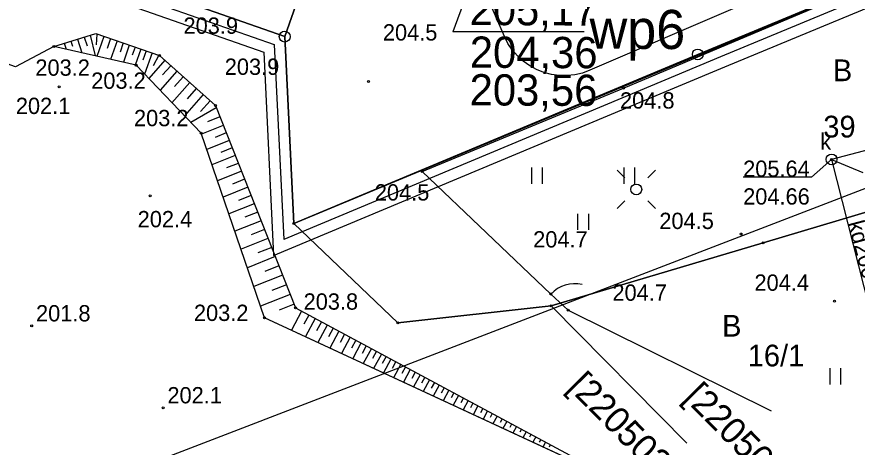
# Model space of a CAD drawing. Extents: x 6512606 to 6513347, y 6022524 to 6022728.
# Drawn here: x 6512793.86 to 6512832.56, y 6022553.23 to 6022573.02 of the extents above; entities that cross this region are included whole.
import ezdxf

# ---------------------------------------------------------------- set-up
doc = ezdxf.new("R2010")
doc.units = 0
for name, color, linetype in [('000 Inne (niezydentyfikowane)', 7, 'Continuous'), ('20', 7, 'Continuous'), ('202-punkt graniczny', 7, 'Continuous'), ('203-punkt graniczny', 7, 'Continuous'), ('208-opis obrębu', 7, 'Continuous'), ('210-oznaczenie konturu użytku gruntowego', 7, 'Continuous'), ('211-numer działki ewidencyjnej', 7, 'Continuous'), ('216-obręb ewidencyjny', 7, 'Continuous'), ('217-kontur klasyfikacyjny', 7, 'Continuous'), ('218-kontur użytku gruntowego', 7, 'Continuous'), ('219-działka ewidencyjna', 7, 'Continuous'), ('4', 7, 'Continuous'), ('940-Trawnik symb.', 7, 'Continuous'), ('940-Trawnik symb. poj.', 7, 'Continuous'), ('Default', 7, 'Continuous'), ('furtka', 7, 'Continuous'), ('kolor_kostka_bet', 7, 'Continuous'), ('latarnia na słupie lub maszcie (punkt)', 7, 'Continuous'), ('Level 47', 7, 'Continuous'), ('maxp_ramka_2', 7, 'Continuous'), ('Obszar opracowania', 7, 'Continuous'), ('ogrodzenie trwałe', 7, 'Continuous'), ('pikieta naturalna', 7, 'Continuous'), ('pikieta naturalna-Atr2', 7, 'Continuous'), ('przewód kanalizacyjny (linia)', 7, 'Continuous'), ('przewód kanalizacyjny (linia)-Atr1', 7, 'Continuous'), ('punkt o określonej wysokości (sieć kanalizacyjna)', 7, 'Continuous'), ('punkt o określonej wysokości (sieć kanalizacyjna)-Atr2', 7, 'Continuous'), ('punkt o określonej wysokości (sieć kanalizacyjna)-Atr3', 7, 'Continuous'), ('punkt wysokościowy naturalny', 7, 'Continuous'), ('punkt wysokościowy naturalny-Atr2', 7, 'Continuous'), ('skarpa nieumocniona', 7, 'Continuous'), ('słup (punkt)', 7, 'Continuous'), ('urządzenie techniczne projektowane lub w budowie (sieć kanalizacyjna) - powierzchnia - ob. projektowany', 7, 'Continuous'), ('woda stojąca', 7, 'Continuous'), ('właz okrągły - siec kanalizacyjna (punkt)', 7, 'Continuous'), ('właz okrągły - siec kanalizacyjna (punkt)-Atr17', 7, 'Continuous')]:
    doc.layers.add(name, color=color, linetype=linetype)

# ---------------------------------------------------------------- blocks, each defined once
blk = doc.blocks.new('202')
at = {"layer": 'Default'}
blk.add_circle((0, 0), 2.5, dxfattribs=at)
blk = doc.blocks.new('203')
at = {"layer": 'Default'}
blk.add_circle((0, 0), 0.45, dxfattribs=at)
blk = doc.blocks.new('PW01')
at = {"layer": 'Default'}
blk.add_circle((0, 0), 0.45, dxfattribs=at)
blk = doc.blocks.new('940')
at = {"layer": 'Default'}
for p, q in [((-23.74, 17.49), (-23.74, 24.99)), ((-18.74, 17.49), (-18.74, 24.99)), ((18.74, 17.49), (18.74, 24.99)), ((23.74, 17.49), (23.74, 24.99)), ((-2.5, -3.75), (-2.5, 3.75)), ((2.5, -3.75), (2.5, 3.75))]:
    blk.add_line(p, q, dxfattribs=at)
blk = doc.blocks.new('SM04')
at = {"layer": 'Default'}
blk.add_circle((0, 0), 2.5, dxfattribs=at)
blk = doc.blocks.new('SM011')
at = {"layer": 'Default'}
for p, q in [((-5.3, 5.31), (-8.83, 8.84)), ((5.31, 5.31), (8.84, 8.84)), ((-5.3, -5.3), (-8.83, -8.83)), ((5.31, -5.3), (8.84, -8.83))]:
    blk.add_line(p, q, dxfattribs=at)
blk = doc.blocks.new('US22')
at = {"layer": 'Default'}
blk.add_circle((0, 0), 2.5, dxfattribs=at)
blk = doc.blocks.new('940P')
at = {"layer": 'Default'}
for p, q in [((-2.5, -3.75), (-2.5, 3.75)), ((2.5, -3.75), (2.5, 3.75))]:
    blk.add_line(p, q, dxfattribs=at)
blk = doc.blocks.new('OK04')
at = {"layer": 'Default'}
blk.add_arc((15, 0.01), 15, 120, 180, dxfattribs=at)

msp = doc.modelspace()

# ---------------------------------------------------------------- linework, layer by layer
at = {"layer": '000 Inne (niezydentyfikowane)'}
for p, q in [((6512796.97, 6022572.09), (6512797.1, 6022571.69)), ((6512797.25, 6022572.17), (6512797.48, 6022571.22)), ((6512797.55, 6022572.23), (6512797.52, 6022571.73)), ((6512797.87, 6022572.12), (6512797.55, 6022571.2)), ((6512796.05, 6022571.81), (6512796.13, 6022571.53)), ((6512796.36, 6022571.9), (6512796.43, 6022571.67)), ((6512796.66, 6022571.99), (6512796.86, 6022571.36)), ((6512798.18, 6022572.02), (6512798.02, 6022571.57)), ((6512798.48, 6022571.91), (6512798.18, 6022571.06)), ((6512798.76, 6022571.82), (6512798.62, 6022571.4)), ((6512799.04, 6022571.72), (6512798.77, 6022570.93)), ((6512799.31, 6022571.63), (6512799.18, 6022571.25)), ((6512799.57, 6022571.54), (6512799.31, 6022570.8)), ((6512799.82, 6022571.45), (6512799.67, 6022571.03)), ((6512800.09, 6022571.36), (6512799.75, 6022570.38)), ((6512800.68, 6022571.02), (6512799.94, 6022570.19)), ((6512800.4, 6022571.25), (6512800.14, 6022570.76)), ((6512801.24, 6022570.52), (6512800.46, 6022569.64)), ((6512800.96, 6022570.77), (6512800.58, 6022570.35)), ((6512801.53, 6022570.26), (6512801.13, 6022569.81)), ((6512801.83, 6022570), (6512801, 6022569.07)), ((6512802.13, 6022569.72), (6512801.71, 6022569.25)), ((6512802.45, 6022569.44), (6512801.58, 6022568.47)), ((6512802.77, 6022569.16), (6512802.32, 6022568.66)), ((6512803.05, 6022568.83), (6512801.88, 6022568.16)), ((6512803.22, 6022568.42), (6512802.64, 6022568.19)), ((6512803.37, 6022568.02), (6512802.37, 6022567.63)), ((6512803.51, 6022567.68), (6512803, 6022567.47)), ((6512803.65, 6022567.33), (6512802.61, 6022566.92)), ((6512803.92, 6022566.64), (6512802.85, 6022566.21)), ((6512803.78, 6022566.99), (6512803.26, 6022566.78)), ((6512804.06, 6022566.28), (6512803.52, 6022566.07)), ((6512804.21, 6022565.92), (6512803.1, 6022565.48)), ((6512804.35, 6022565.55), (6512803.79, 6022565.33)), ((6512804.5, 6022565.18), (6512803.36, 6022564.73)), ((6512804.65, 6022564.8), (6512804.07, 6022564.57)), ((6512804.8, 6022564.42), (6512803.63, 6022563.96)), ((6512804.96, 6022564.03), (6512804.36, 6022563.8)), ((6512805.11, 6022563.64), (6512803.9, 6022563.16)), ((6512805.27, 6022563.23), (6512804.66, 6022562.99)), ((6512805.43, 6022562.83), (6512804.19, 6022562.33)), ((6512805.6, 6022562.41), (6512804.96, 6022562.16)), ((6512805.76, 6022561.99), (6512804.48, 6022561.48)), ((6512805.93, 6022561.57), (6512805.28, 6022561.31)), ((6512806.1, 6022561.13), (6512804.78, 6022560.61)), ((6512806.28, 6022560.69), (6512805.61, 6022560.43)), ((6512806.45, 6022560.25), (6512805.09, 6022559.71)), ((6512806.63, 6022559.8), (6512805.94, 6022559.52)), ((6512806.98, 6022559.48), (6512806.51, 6022558.6)), ((6512807.31, 6022559.3), (6512807.08, 6022558.88)), ((6512807.6, 6022559.15), (6512807.15, 6022558.31)), ((6512807.89, 6022558.99), (6512807.67, 6022558.58)), ((6512808.16, 6022558.84), (6512807.73, 6022558.04)), ((6512808.43, 6022558.7), (6512808.22, 6022558.3)), ((6512808.7, 6022558.56), (6512808.28, 6022557.78)), ((6512808.96, 6022558.42), (6512808.76, 6022558.04)), ((6512809.22, 6022558.28), (6512808.82, 6022557.53)), ((6512809.47, 6022558.15), (6512809.27, 6022557.78)), ((6512809.71, 6022558.01), (6512809.33, 6022557.3)), ((6512809.95, 6022557.89), (6512809.76, 6022557.53)), ((6512810.19, 6022557.76), (6512809.82, 6022557.07)), ((6512810.42, 6022557.64), (6512810.24, 6022557.3)), ((6512810.65, 6022557.51), (6512810.29, 6022556.85)), ((6512810.87, 6022557.39), (6512810.69, 6022557.07)), ((6512811.09, 6022557.27), (6512810.75, 6022556.64)), ((6512811.31, 6022557.16), (6512811.15, 6022556.84)), ((6512811.54, 6022557.04), (6512811.21, 6022556.42)), ((6512811.76, 6022556.92), (6512811.6, 6022556.62)), ((6512811.98, 6022556.8), (6512811.67, 6022556.21)), ((6512812.2, 6022556.68), (6512812.05, 6022556.39)), ((6512812.43, 6022556.56), (6512812.13, 6022556)), ((6512812.65, 6022556.44), (6512812.5, 6022556.17)), ((6512812.87, 6022556.32), (6512812.58, 6022555.79)), ((6512813.09, 6022556.2), (6512812.95, 6022555.94)), ((6512813.31, 6022556.08), (6512813.04, 6022555.57)), ((6512813.54, 6022555.96), (6512813.4, 6022555.71)), ((6512813.76, 6022555.84), (6512813.5, 6022555.36)), ((6512813.98, 6022555.72), (6512813.86, 6022555.49)), ((6512814.2, 6022555.6), (6512813.96, 6022555.15)), ((6512814.43, 6022555.49), (6512814.31, 6022555.26)), ((6512814.65, 6022555.37), (6512814.42, 6022554.94)), ((6512814.87, 6022555.25), (6512814.76, 6022555.04)), ((6512815.09, 6022555.13), (6512814.88, 6022554.72)), ((6512815.32, 6022555.01), (6512815.21, 6022554.81)), ((6512815.54, 6022554.89), (6512815.34, 6022554.51)), ((6512815.76, 6022554.77), (6512815.66, 6022554.59)), ((6512815.98, 6022554.65), (6512815.79, 6022554.3)), ((6512816.21, 6022554.53), (6512816.12, 6022554.36)), ((6512816.43, 6022554.41), (6512816.25, 6022554.08)), ((6512816.65, 6022554.29), (6512816.57, 6022554.13)), ((6512816.87, 6022554.17), (6512816.71, 6022553.87)), ((6512817.1, 6022554.05), (6512817.02, 6022553.91)), ((6512817.32, 6022553.93), (6512817.17, 6022553.66)), ((6512817.54, 6022553.81), (6512817.47, 6022553.68)), ((6512817.76, 6022553.7), (6512817.63, 6022553.45)), ((6512817.99, 6022553.58), (6512817.92, 6022553.46)), ((6512818.21, 6022553.46), (6512818.09, 6022553.23)), ((6512818.43, 6022553.34), (6512818.37, 6022553.23))]:
    msp.add_line(p, q, dxfattribs=at)
at = {"layer": '20'}
for p in [(6512818.017, 6022583.64), (6512819.992, 6022572.326)]:
    msp.add_line(p, (6512813.949, 6022572.326), dxfattribs=at)
at = {"layer": '216-obręb ewidencyjny'}
for points in [[(6512836.687, 6022675.173), (6512833.61, 6022675.02), (6512828.67, 6022670.98), (6512801.96, 6022670.34), (6512810.18, 6022663.28), (6512825.37, 6022649.66), (6512838.47, 6022634.29), (6512852.25, 6022608.25), (6512853.17, 6022604.51), (6512855.78, 6022583.95), (6512858.85, 6022571.74), (6512828.23, 6022562.62), (6512818.47, 6022559.72), (6512824.714, 6022553.406)], [(6512728.286, 6022540.131), (6512737.69, 6022552.74), (6512751.08, 6022569.37), (6512775.81, 6022564.08), (6512780.7, 6022581.02), (6512806.2, 6022572.11), (6512806.62, 6022563.51), (6512811.41, 6022558.95), (6512818.47, 6022559.72), (6512828.23, 6022562.62), (6512858.85, 6022571.74), (6512855.78, 6022583.95), (6512853.17, 6022604.51), (6512852.25, 6022608.25), (6512838.47, 6022634.29)], [(6512824.714, 6022553.406), (6512818.47, 6022559.72), (6512811.41, 6022558.95), (6512806.62, 6022563.51), (6512806.2, 6022572.11), (6512780.7, 6022581.02), (6512775.81, 6022564.08), (6512751.08, 6022569.37)]]:
    msp.add_lwpolyline(points, dxfattribs=at)
at = {"layer": '217-kontur klasyfikacyjny'}
for points in [[(6512811.09, 6022586.02), (6512806.2, 6022572.11)], [(6512825.22, 6022571.29), (6512855.78, 6022583.95)], [(6512806.2, 6022572.11), (6512806.62, 6022563.51)], [(6512806.62, 6022563.51), (6512825.22, 6022571.29)]]:
    msp.add_lwpolyline(points, dxfattribs=at)
at = {"layer": '218-kontur użytku gruntowego'}
for points in [[(6512806.2, 6022572.11), (6512811.09, 6022586.02)], [(6512811.09, 6022586.02), (6512806.2, 6022572.11)], [(6512825.22, 6022571.29), (6512855.78, 6022583.95)], [(6512855.78, 6022583.95), (6512825.22, 6022571.29)], [(6512780.7, 6022581.02), (6512806.2, 6022572.11)], [(6512806.2, 6022572.11), (6512780.7, 6022581.02)], [(6512806.2, 6022572.11), (6512806.62, 6022563.51)], [(6512806.62, 6022563.51), (6512806.2, 6022572.11)], [(6512858.85, 6022571.74), (6512828.23, 6022562.62)], [(6512828.23, 6022562.62), (6512858.85, 6022571.74)], [(6512806.62, 6022563.51), (6512825.22, 6022571.29)], [(6512825.22, 6022571.29), (6512806.62, 6022563.51)], [(6512806.62, 6022563.51), (6512811.41, 6022558.95)], [(6512811.41, 6022558.95), (6512806.62, 6022563.51)], [(6512828.23, 6022562.62), (6512818.47, 6022559.72)], [(6512818.47, 6022559.72), (6512828.23, 6022562.62)], [(6512811.41, 6022558.95), (6512818.47, 6022559.72)], [(6512818.47, 6022559.72), (6512811.41, 6022558.95)], [(6512818.47, 6022559.72), (6512824.714, 6022553.406)], [(6512824.714, 6022553.406), (6512818.47, 6022559.72)]]:
    msp.add_lwpolyline(points, dxfattribs=at)
at = {"layer": '219-działka ewidencyjna'}
for points in [[(6512811.09, 6022586.02), (6512806.2, 6022572.11)], [(6512825.22, 6022571.29), (6512855.78, 6022583.95)], [(6512780.7, 6022581.02), (6512806.2, 6022572.11)], [(6512806.2, 6022572.11), (6512806.62, 6022563.51)], [(6512858.85, 6022571.74), (6512828.23, 6022562.62)], [(6512825.22, 6022571.29), (6512806.62, 6022563.51)], [(6512806.62, 6022563.51), (6512811.41, 6022558.95)], [(6512828.23, 6022562.62), (6512818.47, 6022559.72)], [(6512818.47, 6022559.72), (6512811.41, 6022558.95)], [(6512818.47, 6022559.72), (6512824.714, 6022553.406)]]:
    msp.add_lwpolyline(points, dxfattribs=at)
at = {"layer": '4'}
for points in [[(6512811.09, 6022586.02), (6512806.2, 6022572.11)], [(6512825.22, 6022571.29), (6512855.78, 6022583.95)], [(6512780.7, 6022581.02), (6512806.2, 6022572.11)], [(6512806.2, 6022572.11), (6512806.62, 6022563.51)], [(6512858.85, 6022571.74), (6512828.23, 6022562.62)], [(6512825.22, 6022571.29), (6512806.62, 6022563.51)], [(6512806.62, 6022563.51), (6512811.41, 6022558.95)], [(6512828.23, 6022562.62), (6512818.47, 6022559.72)], [(6512818.47, 6022559.72), (6512811.41, 6022558.95)], [(6512818.47, 6022559.72), (6512824.714, 6022553.406)]]:
    msp.add_lwpolyline(points, dxfattribs=at)
at = {"layer": 'furtka'}
msp.add_lwpolyline([(6512818.46, 6022560.27), (6512819.25, 6022559.53)], dxfattribs=at)
at = {"layer": 'kolor_kostka_bet'}
msp.add_lwpolyline([(6512773.05, 6022582.65), (6512780.7, 6022581.02), (6512806.2, 6022572.11), (6512806.62, 6022563.51), (6512855.78, 6022583.95)], dxfattribs=at)
msp.add_lwpolyline([(6512773.05, 6022582.65), (6512780.7, 6022581.02), (6512806.2, 6022572.11), (6512806.62, 6022563.51), (6512855.78, 6022583.95)], dxfattribs=at)
at = {"layer": 'maxp_ramka_2'}
for points in [[(6512856.423, 6022583.675), (6512826.273, 6022571.185), (6512822.563, 6022569.637), (6512806.155, 6022562.774)], [(6512805.691, 6022562.037), (6512822.756, 6022569.175), (6512826.465, 6022570.723), (6512855.56, 6022582.776)], [(6512780.565, 6022580.538), (6512805.717, 6022571.749), (6512806.155, 6022562.774)], [(6512780.43, 6022580.055), (6512805.234, 6022571.388), (6512805.691, 6022562.037)]]:
    msp.add_lwpolyline(points, dxfattribs=at)
at = {"layer": 'Obszar opracowania'}
msp.add_lwpolyline([(6512710.98, 6022693.84), (6512748.35, 6022694.16), (6512798.11, 6022695.25), (6512807.47, 6022695.46), (6512809.66, 6022606.87), (6512863.71, 6022622.03), (6512875.13, 6022581.36), (6512755.22, 6022535.25), (6512691.61, 6022568.03), (6512709.16, 6022605.16)], close=True, dxfattribs=at)
at = {"layer": 'ogrodzenie trwałe'}
for points in [[(6512818.46, 6022560.27), (6512812.53, 6022565.9), (6512821.8, 6022569.74), (6512835.02, 6022575.32), (6512844.28, 6022579.16), (6512845.12, 6022578.38)], [(6512819.25, 6022559.53), (6512828.604, 6022554.902)]]:
    msp.add_lwpolyline(points, dxfattribs=at)
at = {"layer": 'przewód kanalizacyjny (linia)'}
for points in [[(6512843.16, 6022569.56), (6512831.38, 6022566.46)], [(6512831.38, 6022566.46), (6512832.82, 6022565.86)], [(6512831.38, 6022566.46), (6512833.62, 6022557.64), (6512833.806, 6022556.902)]]:
    msp.add_lwpolyline(points, dxfattribs=at)
at = {"layer": 'punkt o określonej wysokości (sieć kanalizacyjna)-Atr2'}
msp.add_lwpolyline([(6512831.38, 6022566.46), (6512830.45, 6022565.65), (6512827.309, 6022565.65)], dxfattribs=at)
at = {"layer": 'skarpa nieumocniona'}
msp.add_lwpolyline([(6512800.44, 6022571.24), (6512803.01, 6022568.94), (6512806.7, 6022559.63), (6512820.98, 6022551.97), (6512820.89, 6022551.93), (6512805.27, 6022559.18), (6512802.35, 6022567.67), (6512799.36, 6022570.79), (6512795.57, 6022571.66), (6512797.5, 6022572.25)], close=True, dxfattribs=at)
msp.add_lwpolyline([(6512800.44, 6022571.24), (6512803.01, 6022568.94), (6512806.7, 6022559.63), (6512820.98, 6022551.97), (6512820.89, 6022551.93), (6512805.27, 6022559.18), (6512802.35, 6022567.67), (6512799.36, 6022570.79), (6512795.57, 6022571.66), (6512797.5, 6022572.25)], close=True, dxfattribs=at)
at = {"layer": 'urządzenie techniczne projektowane lub w budowie (sieć kanalizacyjna) - powierzchnia - ob. projektowany'}
msp.add_lwpolyline([(6512852.09, 6022584.23), (6512820.25, 6022570.56), (6512819.91, 6022570.43), (6512819.56, 6022570.35), (6512819.2, 6022570.32), (6512818.84, 6022570.32), (6512818.48, 6022570.37), (6512818.13, 6022570.46), (6512817.79, 6022570.6), (6512817.48, 6022570.77), (6512817.18, 6022570.98), (6512816.92, 6022571.23), (6512816.68, 6022571.5), (6512816.48, 6022571.8), (6512816.32, 6022572.12), (6512815.45, 6022574.14)], dxfattribs=at)
at = {"layer": 'woda stojąca'}
msp.add_lwpolyline([(6512822.08, 6022551.38), (6512805.27, 6022559.18), (6512802.35, 6022567.67), (6512799.36, 6022570.79), (6512795.57, 6022571.66), (6512793.8, 6022570.72), (6512788.79, 6022572.53), (6512778.27, 6022575.8), (6512775.8, 6022576.99), (6512772.41, 6022579.75), (6512771.62, 6022580.04), (6512770.3, 6022579.81), (6512769.49, 6022580.02), (6512768.52, 6022578.94)], dxfattribs=at)

# ---------------------------------------------------------------- block references
at = {"layer": '202-punkt graniczny', "xscale": 0.1, "yscale": 0.10000000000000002}
for p in [(6512806.2, 6022572.11), (6512825.22, 6022571.29)]:
    msp.add_blockref('202', p, dxfattribs=at)
at = {"layer": '203-punkt graniczny', "xscale": 0.1, "yscale": 0.10000000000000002}
for p in [(6512806.62, 6022563.51), (6512828.23, 6022562.62), (6512818.47, 6022559.72), (6512811.41, 6022558.95)]:
    msp.add_blockref('203', p, dxfattribs=at)
at = {"layer": '940-Trawnik symb.', "xscale": 0.1, "yscale": 0.10000000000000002}
msp.add_blockref('940', (6512819.95, 6022563.59), dxfattribs=at)
at = {"layer": '940-Trawnik symb. poj.', "xscale": 0.1, "yscale": 0.10000000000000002}
msp.add_blockref('940P', (6512831.56, 6022556.49), dxfattribs=at)
at = {"layer": 'furtka', "xscale": 0.1, "yscale": 0.09999999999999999, "rotation": -43.128}
msp.add_blockref('OK04', (6512818.46, 6022560.27), dxfattribs=at)
at = {"layer": 'latarnia na słupie lub maszcie (punkt)', "xscale": 0.1, "yscale": 0.10000000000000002}
msp.add_blockref('SM011', (6512822.39, 6022565.08), dxfattribs=at)
at = {"layer": 'pikieta naturalna', "xscale": 0.1, "yscale": 0.10000000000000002}
for p in [(6512795.57, 6022571.66), (6512800.44, 6022571.24), (6512799.36, 6022570.79), (6512795.82, 6022569.8), (6512810.06, 6022570.05), (6512821.8, 6022569.74), (6512803.01, 6022568.94), (6512802.35, 6022567.67), (6512812.53, 6022565.9), (6512800.01, 6022564.79), (6512818.46, 6022560.27), (6512806.7, 6022559.63), (6512819.25, 6022559.53), (6512805.27, 6022559.18), (6512794.55, 6022558.81), (6512800.6, 6022555.04)]:
    msp.add_blockref('PW01', p, dxfattribs=at)
at = {"layer": 'punkt o określonej wysokości (sieć kanalizacyjna)', "xscale": 0.1, "yscale": 0.10000000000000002}
msp.add_blockref('PW01', (6512831.38, 6022566.46), dxfattribs=at)
at = {"layer": 'punkt wysokościowy naturalny', "xscale": 0.1, "yscale": 0.10000000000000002}
for p in [(6512827.22, 6022563.03), (6512831.52, 6022559.94)]:
    msp.add_blockref('PW01', p, dxfattribs=at)
at = {"layer": 'słup (punkt)', "xscale": 0.1, "yscale": 0.10000000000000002}
msp.add_blockref('SM04', (6512822.39, 6022565.08), dxfattribs=at)
at = {"layer": 'właz okrągły - siec kanalizacyjna (punkt)', "xscale": 0.1, "yscale": 0.10000000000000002}
msp.add_blockref('US22', (6512831.38, 6022566.46), dxfattribs=at)

# ---------------------------------------------------------------- texts
at = {"layer": '208-opis obrębu'}
for s, p in [('[220502_4.0005] 6', (6512819.19, 6022555.96)), ('[220502_4.0008] 8', (6512824.53, 6022555.47))]:
    msp.add_text(s, height=1.2, rotation=314.681, dxfattribs=at).set_placement(p)
at = {"layer": '210-oznaczenie konturu użytku gruntowego'}
for p in [(6512831.44, 6022570.06), (6512826.34, 6022558.31)]:
    msp.add_text('B', height=1, dxfattribs=at).set_placement(p)
at = {"layer": '211-numer działki ewidencyjnej'}
for s, p in [('39', (6512831, 6022567.47)), ('16/1', (6512827.52, 6022556.94))]:
    msp.add_text(s, height=1, dxfattribs=at).set_placement(p)
at = {"layer": '4'}
for s, p in [('39', (6512831, 6022567.47)), ('16/1', (6512827.52, 6022556.94))]:
    msp.add_text(s, height=1, dxfattribs=at).set_placement(p)
at = {"layer": 'Level 47'}
for s, height, p in [('205,17', 1.4377, (6512814.711, 6022572.642)), ('wp6', 1.7971, (6512820.23, 6022571.557)), ('204,36', 1.4377, (6512814.72, 6022570.679)), ('203,56', 1.4377, (6512814.712, 6022568.947))]:
    msp.add_text(s, height=height, rotation=359.7281, dxfattribs=at).set_placement(p)
at = {"layer": 'pikieta naturalna-Atr2'}
for s, p in [('203.9', (6512801.54, 6022572.24)), ('204.5', (6512810.72, 6022571.93)), ('203.2', (6512794.72, 6022570.31)), ('203.9', (6512803.44, 6022570.35)), ('203.2', (6512797.29, 6022569.71)), ('204.8', (6512821.64, 6022568.8)), ('202.1', (6512793.82, 6022568.55)), ('203.2', (6512799.26, 6022567.99)), ('204.5', (6512810.35, 6022564.57)), ('202.4', (6512799.43, 6022563.34)), ('204.7', (6512817.64, 6022562.41)), ('204.7', (6512821.29, 6022559.96)), ('203.8', (6512807.07, 6022559.55)), ('201.8', (6512794.75, 6022559.01)), ('203.2', (6512802.02, 6022559.03)), ('202.1', (6512800.8, 6022555.24))]:
    msp.add_text(s, height=0.75, dxfattribs=at).set_placement(p)
at = {"layer": 'przewód kanalizacyjny (linia)-Atr1'}
msp.add_text('kd200', height=0.75, rotation=285.028, dxfattribs=at).set_placement((6512832.12, 6022563.54))
at = {"layer": 'punkt o określonej wysokości (sieć kanalizacyjna)-Atr2'}
msp.add_text('205.64', height=0.75, dxfattribs=at).set_placement((6512827.309, 6022565.658))
at = {"layer": 'punkt o określonej wysokości (sieć kanalizacyjna)-Atr3'}
msp.add_text('204.66', height=0.75, dxfattribs=at).set_placement((6512827.309, 6022564.383))
at = {"layer": 'punkt wysokościowy naturalny-Atr2'}
for s, p in [('204.5', (6512823.45, 6022563.26)), ('204.4', (6512827.83, 6022560.42))]:
    msp.add_text(s, height=0.75, dxfattribs=at).set_placement(p)
at = {"layer": 'właz okrągły - siec kanalizacyjna (punkt)-Atr17'}
msp.add_text('k', height=0.75, dxfattribs=at).set_placement((6512830.86, 6022566.91))

doc.saveas('drawing.dxf')
